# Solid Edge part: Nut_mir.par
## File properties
Author: Sarvanan
Template: Sync Iso Part.par
Last saved by: Sarvanan
Revision: 2
Application: Solid Edge
Username: Sarvanan
Accuracy: 0.990
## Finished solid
Body 1: solid body, 21 faces, 56 edges, 36 vertices.
  Faces by surface: spun 12, plane 8, cylinder 1
  Edges by curve: circle 18, line 18, intersection 17, spline 3
Bounding box of the edges (mm; curved faces can reach further): 30.022 x 26.000 x 12.000, from (4.7313, -56.9194, 0) to (34.7535, -30.9194, 12).
Cylindrical faces by radius (mm): R6 x1
Planar faces by outward normal: +y 1, +z 1, -y 1, -z 1, oblique 4
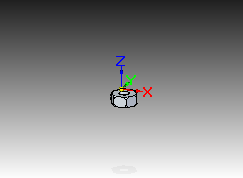
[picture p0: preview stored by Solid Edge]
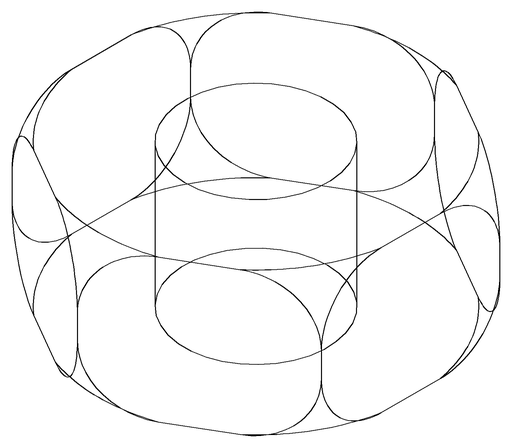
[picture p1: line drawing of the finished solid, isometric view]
